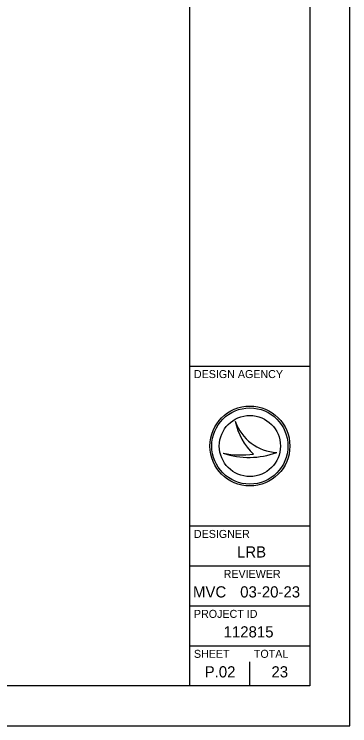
# Model space of a CAD drawing. Extents: x 0 to 34000, y 0 to 22000.
# Drawn here: x 29802 to 34000, y 0 to 8902 of the extents above; entities that cross this region are included whole.
import ezdxf

# ---------------------------------------------------------------- set-up
doc = ezdxf.new("R2010")
doc.units = 0
for name, color, linetype in [('SH_Border', 7, 'Continuous'), ('SH_Cut_Line', 7, 'Continuous'), ('SH_Data', 7, 'Continuous')]:
    doc.layers.add(name, color=color, linetype=linetype)

msp = doc.modelspace()

# ---------------------------------------------------------------- linework, layer by layer
at = {"layer": 'SH_Border'}
for p, q in [((32000, 500), (32000, 21500)), ((32000, 4500), (33500, 4500)), ((32000, 2500), (33500, 2500)), ((32000, 2000), (33500, 2000)), ((32000, 1500), (33500, 1500)), ((32000, 1000), (33500, 1000))]:
    msp.add_line(p, q, dxfattribs=at)
msp.add_lwpolyline([(1500, 21500), (33500, 21500), (33500, 500), (1500, 500)], close=True, dxfattribs=at)
at = {"layer": 'SH_Cut_Line'}
msp.add_lwpolyline([(0, 0), (34000, 0), (34000, 22000), (0, 22000)], close=True, dxfattribs=at)
at = {"layer": 'SH_Data'}
for p, q in [((32567.4, 3809.6), (32567.5, 3809.6)), ((32750, 3500), (32750, 3500)), ((32417.2, 3409.5), (32417.2, 3409.5)), ((33087.3, 3418.5), (33087.3, 3418.5)), ((32750, 500), (32750, 800)), ((32375, 675), (32375, 675))]:
    msp.add_line(p, q, dxfattribs=at)
for radius in [500, 476.8, 476.8, 382.2]:
    msp.add_circle((32750, 3500), radius, dxfattribs=at)
for centre, radius, start, end in [((33115.9, 3997.6), 579.8, 198.92567, 198.93195), ((33346.7, 3970.1), 795.6, 191.63793, 191.64215), ((33115.9, 3997.6), 579.8, 198.93195, 267.16574), ((33346.7, 3970.1), 795.6, 191.64215, 226.09467), ((32739.4, 4370), 1013.1, 251.45764, 290.08324), ((32648, 4654.3), 1266.1, 259.49639, 259.49952), ((32739.4, 4370), 1013.1, 251.45274, 251.45764), ((32648, 4654.3), 1266.1, 259.49952, 276.66723)]:
    msp.add_arc(centre, radius, start, end, dxfattribs=at)

# ---------------------------------------------------------------- texts
for s, height, p in [('DESIGN AGENCY', 100, (32050, 4350)), ('DESIGNER', 100, (32050, 2350)), ('LRB', 140, (32588.6, 2105)), ('REVIEWER', 100, (32421.8, 1850)), ('MVC', 140, (32038.3, 1605)), ('03-20-23', 140, (32628.9, 1605)), ('PROJECT ID', 100, (32050, 1350)), ('112815', 140, (32421.2, 1105)), ('SHEET', 100, (32050, 850)), ('TOTAL', 100, (32800, 850)), ('P.02', 140, (32184.5, 605)), ('23', 140, (33020, 605))]:
    msp.add_text(s, height=height, dxfattribs=at).set_placement(p)

doc.saveas('drawing.dxf')
